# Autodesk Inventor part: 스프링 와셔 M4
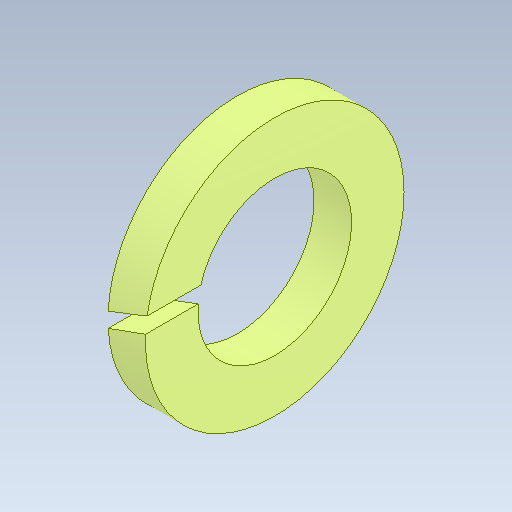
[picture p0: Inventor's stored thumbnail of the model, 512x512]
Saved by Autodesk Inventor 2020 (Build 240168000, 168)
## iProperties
Created: 2024-05
Part Number: 스프링 와셔 M4
Material: 강철, 연강
Description: 스프링 잠금 와셔
Document SubType Name: Modeling
Designer: oem
Density: 7.85 g/cm^3
Appearance: 기본값
Author: jhkim
Sending System: Autodesk Inventor 2025
Preprocessor: ST-DEVELOPER v20
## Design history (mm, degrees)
feature "Solid1"
node "솔리드1"
